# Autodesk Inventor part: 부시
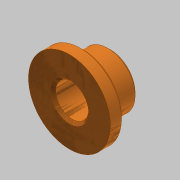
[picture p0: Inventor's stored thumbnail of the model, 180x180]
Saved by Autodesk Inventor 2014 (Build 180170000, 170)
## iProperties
Created: 2016-02
Part Number: 부시
Material: 스테인리스강
Document SubType Name: Modeling
Designer: mduedu
Density: 8.08 g/cm^3
Appearance: 금속 1600F 열
Author: mduedu
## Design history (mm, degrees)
sketch "스케치1"
  geometry: C1 r 15 at (0, 0); 1 further point
  constraints: 1 centre point, 1 coincident
  dimensions: "d0" = 30 diameter of C1
extrude "돌출1" new body sketch "스케치1" distance "d1" = 5; taper "d2" = 0 deg
sketch "스케치2"
  geometry: C1 r 10 at (0, 0); 1 further point
  constraints: 1 centre point, 1 coincident
  dimensions: "d3" = 20 diameter of C1
extrude "돌출2" join sketch "스케치2" distance "d4" = 10; taper "d5" = 0 deg
hole "구멍1" diameter "d8" = 12; stored, may be unused: countersink angle "d12" = 90 deg, drill point angle "d14" = 118 deg; dims "d9" = 6, "d10" = 4, "d11" = 2, "d13" = 8, "d15" = 10, "d16" = 10
chamfer "모따기1" distance "d17" = 1; stored, may be unused: second distance "d18" = 2, angle "d19" = 45 deg
chamfer "모따기2" distance "d20" = 1; stored, may be unused: second distance "d21" = 2, angle "d22" = 45 deg
chamfer "모따기3" distance "d23" = 1; stored, may be unused: second distance "d24" = 2, angle "d25" = 45 deg
node "솔리드1"
